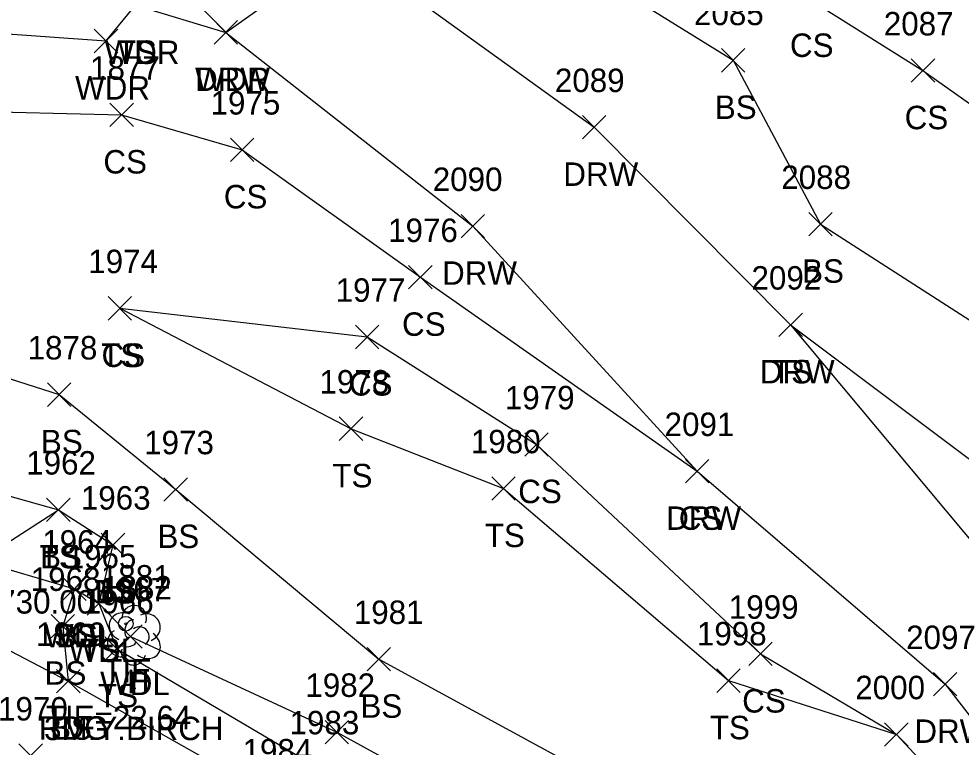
# Model space of a CAD drawing. Extents: x 1512665 to 1513714, y 110636 to 112816.
# Drawn here: x 1512834.1 to 1512914.5, y 110869.1 to 110931.3 of the extents above; entities that cross this region are included whole.
import ezdxf

# ---------------------------------------------------------------- set-up
doc = ezdxf.new("R2010")
doc.units = 0
for name, color, linetype in [('C_A', 7, 'Continuous'), ('C_C', 7, 'Continuous'), ('C_I', 7, 'Continuous'), ('CBP', 7, 'Continuous'), ('L_A', 7, 'Continuous'), ('L_C', 7, 'Continuous'), ('L_I', 7, 'Continuous'), ('L_TIC', 7, 'Continuous'), ('LAWA', 7, 'Continuous'), ('LELB', 7, 'Continuous'), ('LTD', 7, 'Continuous'), ('P_A', 7, 'Continuous'), ('P_I', 7, 'Continuous'), ('P_TIC', 7, 'Continuous'), ('PEU', 7, 'Continuous'), ('R_A', 7, 'Continuous'), ('R_I', 7, 'Continuous'), ('R_TIC', 7, 'Continuous'), ('RDW', 7, 'Continuous')]:
    doc.layers.add(name, color=color, linetype=linetype)

msp = doc.modelspace()

# ---------------------------------------------------------------- linework, layer by layer
at = {"layer": 'CBP'}
for radius in [0.625, 0.0833]:
    msp.add_circle((1512843.266, 110879.667), radius, dxfattribs=at)
at = {"layer": 'L_TIC'}
for points in [[(1512850.809, 110929.104), (1512852.809, 110931.104)], [(1512852.809, 110929.104), (1512850.809, 110931.104)], [(1512840.584, 110928.37), (1512842.584, 110930.37)], [(1512842.584, 110928.37), (1512840.584, 110930.37)], [(1512894.063, 110926.72), (1512896.063, 110928.72)], [(1512896.063, 110926.72), (1512894.063, 110928.72)], [(1512910.254, 110925.844), (1512912.254, 110927.844)], [(1512912.254, 110925.844), (1512910.254, 110927.844)], [(1512841.917, 110922.066), (1512843.917, 110924.066)], [(1512843.917, 110922.066), (1512841.917, 110924.066)], [(1512852.188, 110919.094), (1512854.188, 110921.094)], [(1512854.188, 110919.094), (1512852.188, 110921.094)], [(1512901.508, 110912.749), (1512903.508, 110914.749)], [(1512903.508, 110912.749), (1512901.508, 110914.749)], [(1512867.389, 110908.222), (1512869.389, 110910.222)], [(1512869.389, 110908.222), (1512867.389, 110910.222)], [(1512841.758, 110905.569), (1512843.758, 110907.569)], [(1512843.758, 110905.569), (1512841.758, 110907.569)], [(1512841.758, 110905.569), (1512843.758, 110907.569)], [(1512843.758, 110905.569), (1512841.758, 110907.569)], [(1512898.968, 110904.165), (1512900.968, 110906.165)], [(1512900.968, 110904.165), (1512898.968, 110906.165)], [(1512862.861, 110903.126), (1512864.861, 110905.126)], [(1512864.861, 110903.126), (1512862.861, 110905.126)], [(1512836.589, 110898.205), (1512838.589, 110900.205)], [(1512838.589, 110898.205), (1512836.589, 110900.205)], [(1512861.479, 110895.303), (1512863.479, 110897.303)], [(1512863.479, 110895.303), (1512861.479, 110897.303)], [(1512877.296, 110893.952), (1512879.296, 110895.952)], [(1512879.296, 110893.952), (1512877.296, 110895.952)], [(1512890.99, 110891.675), (1512892.99, 110893.675)], [(1512892.99, 110891.675), (1512890.99, 110893.675)], [(1512846.527, 110890.123), (1512848.527, 110892.123)], [(1512848.527, 110890.123), (1512846.527, 110892.123)], [(1512846.527, 110890.123), (1512848.527, 110892.123)], [(1512848.527, 110890.123), (1512846.527, 110892.123)], [(1512874.479, 110890.206), (1512876.479, 110892.206)], [(1512876.479, 110890.206), (1512874.479, 110892.206)], [(1512836.516, 110888.389), (1512838.516, 110890.389)], [(1512838.516, 110888.389), (1512836.516, 110890.389)], [(1512836.516, 110888.389), (1512838.516, 110890.389)], [(1512838.516, 110888.389), (1512836.516, 110890.389)], [(1512841.176, 110885.401), (1512843.176, 110887.401)], [(1512843.176, 110885.401), (1512841.176, 110887.401)], [(1512841.176, 110885.401), (1512843.176, 110887.401)], [(1512843.176, 110885.401), (1512841.176, 110887.401)], [(1512837.882, 110881.648), (1512839.882, 110883.648)], [(1512839.882, 110881.648), (1512837.882, 110883.648)], [(1512837.882, 110881.648), (1512839.882, 110883.648)], [(1512839.882, 110881.648), (1512837.882, 110883.648)], [(1512839.963, 110880.395), (1512841.963, 110882.395)], [(1512841.963, 110880.395), (1512839.963, 110882.395)], [(1512839.963, 110880.395), (1512841.963, 110882.395)], [(1512841.963, 110880.395), (1512839.963, 110882.395)], [(1512836.903, 110878.466), (1512838.903, 110880.466)], [(1512838.903, 110878.466), (1512836.903, 110880.466)], [(1512842.663, 110877.579), (1512844.663, 110879.579)], [(1512844.663, 110877.579), (1512842.663, 110879.579)], [(1512841.492, 110876.537), (1512843.492, 110878.537)], [(1512843.492, 110876.537), (1512841.492, 110878.537)], [(1512863.842, 110875.646), (1512865.842, 110877.646)], [(1512865.842, 110875.646), (1512863.842, 110877.646)], [(1512896.396, 110876.091), (1512898.396, 110878.091)], [(1512898.396, 110876.091), (1512896.396, 110878.091)], [(1512837.367, 110873.777), (1512839.367, 110875.777)], [(1512839.367, 110873.777), (1512837.367, 110875.777)], [(1512893.667, 110873.814), (1512895.667, 110875.814)], [(1512895.667, 110873.814), (1512893.667, 110875.814)], [(1512860.274, 110869.427), (1512862.274, 110871.427)], [(1512862.274, 110869.427), (1512860.274, 110871.427)], [(1512907.986, 110869.229), (1512909.986, 110871.229)], [(1512909.986, 110869.229), (1512907.986, 110871.229)], [(1512907.986, 110869.229), (1512909.986, 110871.229)], [(1512909.986, 110869.229), (1512907.986, 110871.229)]]:
    msp.add_lwpolyline(points, dxfattribs=at)
at = {"layer": 'LAWA'}
for points in [[(1512760.327, 110918.9), (1512772.715, 110925.351), (1512775.007, 110936.434), (1512792.554, 110938.683), (1512803.23, 110932.988), (1512815.948, 110931.191), (1512841.584, 110929.37), (1512844.095, 110932.413), (1512851.809, 110930.104), (1512861.965, 110937.336), (1512864.411, 110940.492), (1512867.897, 110945.243), (1512874.74, 110954.614), (1512875.763, 110966.444), (1512876.134, 110982.426), (1512872.076, 110997.369), (1512855.488, 111002.566), (1512840.685, 111007.355)], [(1512760.327, 110918.9), (1512789.467, 110902.153), (1512813.998, 110894.649), (1512829.426, 110887.292), (1512830.768, 110885.044), (1512838.882, 110882.648), (1512840.963, 110881.395), (1512843.663, 110878.579), (1512861.274, 110870.427), (1512887.257, 110856.133), (1512901.813, 110849.485), (1512918.081, 110842.567)]]:
    msp.add_lwpolyline(points, dxfattribs=at)
at = {"layer": 'LELB'}
for points in [[(1512867.091, 110954.959), (1512866.028, 110951.273), (1512867.897, 110945.243), (1512874.787, 110940.291), (1512895.063, 110927.72), (1512902.508, 110913.749), (1512928.484, 110897.044), (1512945.574, 110871.654), (1512953.444, 110855.33), (1512967.722, 110840.945), (1512974.771, 110829.535), (1512966.081, 110822.54), (1512959.925, 110816.123)], [(1512721.894, 110948.789), (1512722.497, 110942.68), (1512730.744, 110933.358), (1512741.905, 110924.629), (1512760.327, 110918.9), (1512788.256, 110897.799), (1512812.95, 110889.365), (1512823.675, 110884.08), (1512829.426, 110887.292), (1512828.602, 110891.881), (1512837.516, 110889.389), (1512842.176, 110886.401), (1512840.963, 110881.395), (1512842.492, 110877.537), (1512859.927, 110867.233), (1512885.327, 110852.839), (1512900.342, 110845.897), (1512916.833, 110839.511), (1512931.348, 110831.636), (1512947.325, 110821.384)], [(1512874.787, 110940.291), (1512901.473, 110933.009), (1512911.254, 110926.844), (1512935.137, 110909.972), (1512951.516, 110893.128), (1512955.624, 110874.23), (1512953.444, 110855.33)], [(1512772.715, 110925.351), (1512778.581, 110918.536), (1512796.221, 110907.99), (1512810.428, 110907.882), (1512837.589, 110899.205), (1512847.527, 110891.123)], [(1512814.954, 110923.761), (1512842.917, 110923.066), (1512853.188, 110920.094), (1512868.389, 110909.222), (1512891.99, 110892.675)], [(1512842.758, 110906.569), (1512862.479, 110896.303), (1512875.479, 110891.206), (1512894.667, 110874.814), (1512908.986, 110870.229), (1512923.212, 110854.931), (1512926.272, 110845.461)], [(1512842.758, 110906.569), (1512863.861, 110904.126), (1512878.296, 110894.952), (1512897.396, 110877.091), (1512908.986, 110870.229)], [(1512899.968, 110905.165), (1512920.267, 110889.921), (1512938.022, 110866.04), (1512947.184, 110852.269), (1512966.207, 110831.108), (1512963.612, 110826.617), (1512956.461, 110818.296)], [(1512847.527, 110891.123), (1512864.842, 110876.646), (1512889.749, 110863.082), (1512898.246, 110858.912), (1512926.272, 110845.461), (1512938.494, 110838.55)], [(1512823.675, 110884.08), (1512830.768, 110885.044), (1512837.516, 110889.389)], [(1512842.176, 110886.401), (1512838.882, 110882.648), (1512837.903, 110879.466), (1512838.367, 110874.777)]]:
    msp.add_lwpolyline(points, dxfattribs=at)
at = {"layer": 'LTD'}
msp.add_line((1512843.939, 110878.737), (1512843.939, 110878.737), dxfattribs=at)
msp.add_line((1512843.939, 110878.737), (1512843.939, 110878.737), dxfattribs=at)
msp.add_arc((1512843.986, 110880.171), 1.047, 335.52715, 180.95627, dxfattribs=at)
for centre, major_axis, ratio, start_param, end_param in [((1512843.147, 110879.404), (1.21, -0.512), 0.895232, 1.570796, 4.712389), ((1512844.98, 110879.321), (-1.141, -0.483), 0.949671, 1.570796, 4.712389), ((1512843.731, 110879.196), (-0.208, -0.792), 0.645439, 3.141593, 6.283185), ((1512842.856, 110878.029), (0.584, -1.042), 0.959034, 3.141593, 6.283185), ((1512844.439, 110878.571), (-0.5, 0.667), 0.989748, 3.141593, 6.283185), ((1512844.939, 110877.904), (-1.09, 0.792), 0.841452, 1.570796, 4.712389), ((1512843.939, 110877.237), (0.265, 1.061), 0.942809, 1.570796, 4.712389), ((1512843.481, 110877.987), (-0.625, -0.083), 0.423636, 0, 3.141593)]:
    msp.add_ellipse(centre, major_axis=major_axis, ratio=ratio, start_param=start_param, end_param=end_param, dxfattribs=at)
at = {"layer": 'P_TIC'}
for points in [[(1512837.367, 110873.777), (1512839.367, 110875.777)], [(1512839.367, 110873.777), (1512837.367, 110875.777)], [(1512834.154, 110867.413), (1512836.154, 110869.413)], [(1512836.154, 110867.413), (1512834.154, 110869.413)]]:
    msp.add_lwpolyline(points, dxfattribs=at)
at = {"layer": 'PEU'}
msp.add_lwpolyline([(1512701.918, 111049.687), (1512700.272, 111027.695), (1512701.575, 110993.777), (1512707.634, 110973.739), (1512708.973, 110956.468), (1512713.567, 110946.899), (1512719.219, 110936.541), (1512726.895, 110929.376), (1512741.614, 110919.596), (1512758.159, 110912.379), (1512787.354, 110896.005), (1512813.053, 110887.984), (1512838.367, 110874.777), (1512855.917, 110864.835), (1512882.817, 110848.349), (1512898.24, 110841.366), (1512913.486, 110833.402), (1512927.92, 110827.382), (1512944.462, 110817.212), (1512962.879, 110803.833), (1512982.126, 110789.052), (1512997.253, 110777.445), (1513011.324, 110770.561), (1513024.004, 110765.991)], dxfattribs=at)
at = {"layer": 'R_TIC'}
for points in [[(1512850.809, 110929.104), (1512852.809, 110931.104)], [(1512852.809, 110929.104), (1512850.809, 110931.104)], [(1512882.211, 110921.012), (1512884.211, 110923.012)], [(1512884.211, 110921.012), (1512882.211, 110923.012)], [(1512871.871, 110912.575), (1512873.871, 110914.575)], [(1512873.871, 110912.575), (1512871.871, 110914.575)], [(1512898.968, 110904.165), (1512900.968, 110906.165)], [(1512900.968, 110904.165), (1512898.968, 110906.165)], [(1512890.99, 110891.675), (1512892.99, 110893.675)], [(1512892.99, 110891.675), (1512890.99, 110893.675)], [(1512912.156, 110873.506), (1512914.156, 110875.506)], [(1512914.156, 110873.506), (1512912.156, 110875.506)]]:
    msp.add_lwpolyline(points, dxfattribs=at)
at = {"layer": 'RDW'}
for points in [[(1512846.807, 110959.221), (1512852.941, 110946.592), (1512861.965, 110937.336), (1512883.211, 110922.012), (1512899.968, 110905.165), (1512926.485, 110873.446), (1512935.332, 110863.205), (1512946.848, 110850.628), (1512960.543, 110832.025), (1512963.612, 110826.617), (1512966.081, 110822.54), (1512965.912, 110813.145), (1512965.768, 110809.049), (1512964.105, 110806.986), (1512962.879, 110803.833)], [(1512831.666, 110950.261), (1512839.34, 110942.793), (1512851.809, 110930.104), (1512872.871, 110913.575), (1512891.99, 110892.675), (1512913.156, 110874.506), (1512928.573, 110854.542), (1512938.494, 110838.55), (1512948.315, 110825.655), (1512947.325, 110821.384), (1512945.804, 110819.115), (1512944.462, 110817.212)]]:
    msp.add_lwpolyline(points, dxfattribs=at)

# ---------------------------------------------------------------- texts
at = {"layer": 'C_A'}
msp.add_text('TIE', height=2, dxfattribs=at).set_placement((1512841.345, 110874.667))
at = {"layer": 'C_C'}
for s, p in [('BM7=RRSIR ELEV: 1730.00', (1512806.451, 110880.533)), ('TIE=22.64', (1512836.447, 110870.667))]:
    msp.add_text(s, height=2, dxfattribs=at).set_placement(p)
at = {"layer": 'C_I'}
msp.add_text('1881', height=2, dxfattribs=at).set_placement((1512841.14, 110882.667))
at = {"layer": 'L_A'}
for s, p in [('CS', (1512899.914, 110928.009)), ('WDR', (1512841.457, 110927.413)), ('TS', (1512842.504, 110927.413)), ('WDR', (1512838.946, 110924.37)), ('WDR', (1512849.172, 110925.104)), ('BS', (1512893.504, 110922.72)), ('CS', (1512909.695, 110921.844)), ('CS', (1512841.358, 110918.066)), ('CS', (1512851.629, 110915.094)), ('BS', (1512900.949, 110908.749)), ('CS', (1512866.83, 110904.222)), ('TS', (1512841.168, 110901.569)), ('CS', (1512841.199, 110901.569)), ('TS', (1512898.378, 110900.165)), ('CS', (1512862.302, 110899.126)), ('BS', (1512836.03, 110894.205)), ('TS', (1512860.889, 110891.303)), ('CS', (1512876.737, 110889.952)), ('CS', (1512890.431, 110887.675)), ('BS', (1512845.968, 110886.123)), ('BS', (1512845.968, 110886.123)), ('TS', (1512873.888, 110886.206)), ('TS', (1512835.925, 110884.389)), ('BS', (1512835.957, 110884.389)), ('TS', (1512840.585, 110881.401)), ('BS', (1512840.617, 110881.401)), ('WDL', (1512836.3, 110877.648)), ('BS', (1512837.323, 110877.648)), ('WDL', (1512838.38, 110876.395)), ('TS', (1512839.372, 110876.395)), ('BS', (1512836.344, 110874.466)), ('H', (1512843.372, 110873.737)), ('WDL', (1512841.081, 110873.579)), ('TS', (1512840.902, 110872.537)), ('CS', (1512895.837, 110872.091)), ('BS', (1512863.283, 110871.646)), ('BS', (1512836.808, 110869.777)), ('TS', (1512893.077, 110869.814))]:
    msp.add_text(s, height=2, dxfattribs=at).set_placement(p)
at = {"layer": 'L_C'}
msp.add_text('3M.Y.BIRCH', height=2, dxfattribs=at).set_placement((1512836.301, 110869.737))
at = {"layer": 'L_I'}
for s, p in [('2085', (1512891.725, 110930.72)), ('2087', (1512907.915, 110929.844)), ('1877', (1512840.224, 110926.066)), ('1975', (1512850.496, 110923.094)), ('2088', (1512899.17, 110916.749)), ('1976', (1512865.641, 110912.222)), ('1974', (1512840.066, 110909.569)), ('1974', (1512840.066, 110909.569)), ('2092', (1512896.63, 110908.165)), ('1977', (1512861.168, 110907.126)), ('1878', (1512834.897, 110902.205)), ('1978', (1512859.787, 110899.303)), ('1979', (1512875.595, 110897.952)), ('2091', (1512889.219, 110895.675)), ('1973', (1512844.835, 110894.123)), ('1973', (1512844.835, 110894.123)), ('1980', (1512872.699, 110894.206)), ('1962', (1512834.775, 110892.389)), ('1962', (1512834.775, 110892.389)), ('1963', (1512839.436, 110889.401)), ('1963', (1512839.436, 110889.401)), ('1964', (1512836.142, 110885.648)), ('1964', (1512836.142, 110885.648)), ('1965', (1512838.223, 110884.395)), ('1965', (1512838.223, 110884.395)), ('1968', (1512835.163, 110882.466)), ('1882', (1512841.246, 110881.737)), ('1967', (1512840.923, 110881.579)), ('1966', (1512839.697, 110880.537)), ('1981', (1512862.716, 110879.646)), ('1999', (1512894.696, 110880.091)), ('1969', (1512835.619, 110877.777)), ('1998', (1512891.974, 110877.814)), ('1982', (1512858.582, 110873.427)), ('2000', (1512905.482, 110873.229)), ('2000', (1512905.482, 110873.229)), ('1983', (1512857.234, 110870.233)), ('1984', (1512853.224, 110867.835))]:
    msp.add_text(s, height=2, dxfattribs=at).set_placement(p)
at = {"layer": 'P_A'}
msp.add_text('RDG', height=2, dxfattribs=at).set_placement((1512835.855, 110869.777))
at = {"layer": 'P_I'}
for s, p in [('1969', (1512835.619, 110877.777)), ('1970', (1512832.374, 110871.413)), ('1984', (1512853.224, 110867.835))]:
    msp.add_text(s, height=2, dxfattribs=at).set_placement(p)
at = {"layer": 'R_A'}
for p in [(1512849.179, 110925.104), (1512880.581, 110917.012), (1512870.241, 110908.575), (1512897.338, 110900.165), (1512889.36, 110887.675), (1512910.526, 110869.506)]:
    msp.add_text('DRW', height=2, dxfattribs=at).set_placement(p)
at = {"layer": 'R_I'}
for s, p in [('2089', (1512879.864, 110925.012)), ('2090', (1512869.446, 110916.575)), ('2092', (1512896.63, 110908.165)), ('2091', (1512889.219, 110895.675)), ('2097', (1512909.817, 110877.506))]:
    msp.add_text(s, height=2, dxfattribs=at).set_placement(p)

doc.saveas('drawing.dxf')
